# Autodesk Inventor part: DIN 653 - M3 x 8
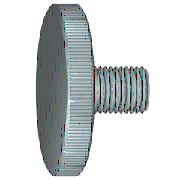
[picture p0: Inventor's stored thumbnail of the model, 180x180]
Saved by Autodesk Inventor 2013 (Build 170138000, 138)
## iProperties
Created: 2012-02
Part Number: DIN 653 - M3 x 8
Material: Stahl, weich
Description: Rändelschraube
Document SubType Name: Modeling
Standard: DIN 653
Designer: rYan
Standards Organization: DIN
Language: de-DE
Size Designation: M3 x 8
Categories: <MemberInstance><Categories><Category DisplayName="Verbindungselemente" InternalName="e4da775c-781d-43d5-af7c-5136215cf5a6" Mnemonic="FSTN"><Category DisplayNam
Density: 1 g/cm^3
IsCustomPart: 0
Author: rYan
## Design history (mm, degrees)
revolve "Körper" stored, may be unused: angle "d8" = 90 deg
node "IDS_WORKPLANE{1}"
workplane "Work Plane2"
body "Solid1"
feature "Gewinde" dims "d2" = 6.224 (= GEL - 0.092 x GD), "d3" = 0
chamfer "Fase1" distance "d10" = 0.3 (= PHH); stored, may be unused: angle "d11" = 45 deg (= FAWI), second distance "d38" = 0.3 (= PHH)
sketch "Skizze1"
  geometry: L1 (-2.5, 0)-(8, 0); L2 (8, 0)-(8, 5); L3 (7.673, 1.5)-(0, 1.5); L4 (0, -1.2)-(0, 7.2) reference; L5 (0, 1.5)-(0, 6); L6 (0, 6)-(-2.5, 6); L7 (-2.5, 6)-(-2.5, 0); L8 (-4.616, 0)-(10.197, 0) reference; A1 r 3.6 centre (4.4, 0) between (8, 0) and (7.673, 1.5)
  constraints: 13 end point, 2 perpendicular, 2 point on circle, 2 vertical alignment, 1 centre point, 1 collinear, 1 parallel, 1 point on line, 1 tangent
  dimensions: "d1" = 3 diameter of L3 L1 (= GD); "d6" = 12 diameter of L6 L1 (= KOD); "d7" = 2.5 distance between parallel lines of L5 L7 (= KOH); "d9" = 3.6 radius of A1 (= 1.2 x GD); "d41" = 8 distance between parallel lines of L2 L5 (= NLG)
other parameters: "GD" = 3 [user parameter; used in 3 equation terms], "NLG" = 8 [user parameter; used in 1 equation term], "GEL" = 6.5 [user parameter; used in 1 equation term], "KOD" = 12 [user parameter; used in 1 equation term], "KOH" = 2.5 [user parameter; used in 2 equation terms], "GAL" = 0.30673 (= 0.61345 x PTC) [user parameter], "d4" = 0, "SD" = 0 [user parameter], "LADI" = 3 (= NND) [user parameter], "PHH" = 0.3 [user parameter; used in 2 equation terms], "FAWI" = 45 deg [user parameter; used in 1 equation term], "d12" = -1.25 (= -0.5 x KOH), "T" = 0.5 [user parameter], "d39" = 0, "d42" = 0, "NND" = 3 [user parameter; used in 1 equation term], "PTC" = 0.5 [user parameter; used in 2 equation terms]
